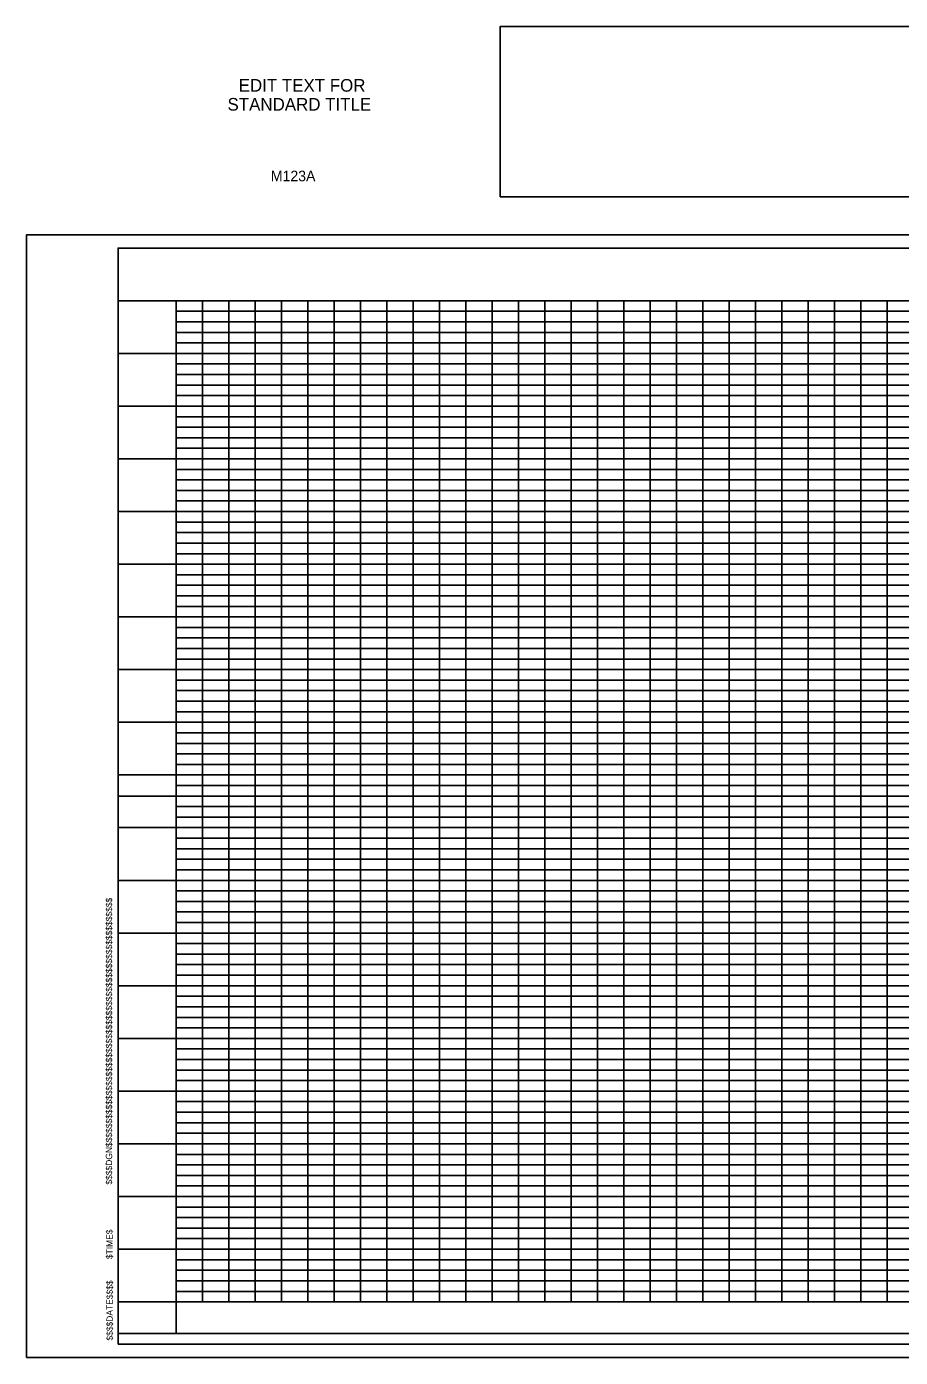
# Model space of a CAD drawing. Extents: x -87 to 1577, y -13 to 1250.
# Drawn here: x -87 to 742, y -13 to 1250 of the extents above; entities that cross this region are included whole.
import ezdxf

# ---------------------------------------------------------------- set-up
doc = ezdxf.new("R2010")
doc.units = 0
for name, color, linetype in [('D_CFL_Clip_Boundary_1', 7, 'Continuous'), ('D_CFL_Clip_Boundary_2', 7, 'Continuous'), ('D_CFL_Sheet_Border_ PlotShape', 7, 'Continuous'), ('D_CFL_Sheet_Border_Base', 7, 'Continuous'), ('D_CFL_Sheet_Border_Plan_Plan', 7, 'Continuous'), ('D_CFL_Sheet_Border_PnP', 7, 'Continuous'), ('D_CFL_Sheet_Border_Profile', 7, 'Continuous')]:
    doc.layers.add(name, color=color, linetype=linetype)

msp = doc.modelspace()

# ---------------------------------------------------------------- linework, layer by layer
at = {"layer": 'D_CFL_Clip_Boundary_1'}
msp.add_lwpolyline([(0, 520), (0, 1040), (1305, 1040), (1305, 1000), (1560, 1000), (1560, 520)], close=True, dxfattribs=at)
at = {"layer": 'D_CFL_Clip_Boundary_2'}
msp.add_lwpolyline([(1505, 520), (55, 520), (55, 40), (1505, 40)], close=True, dxfattribs=at)
at = {"layer": 'D_CFL_Sheet_Border_ PlotShape'}
msp.add_line((-86.9, -12.7), (-86.9, -12.7), dxfattribs=at)
msp.add_lwpolyline([(-86.9, -12.7), (1576.9, -12.7), (1576.9, 1052.6), (-86.9, 1052.6)], close=True, dxfattribs=at)
at = {"layer": 'D_CFL_Sheet_Border_Base'}
for points in [[(362.6, 1088.6), (1560, 1088.6), (1560, 1250.1), (362.6, 1250.1)], [(0, 0), (1560, 0), (1560, 1040), (0, 1040)]]:
    msp.add_lwpolyline(points, close=True, dxfattribs=at)
at = {"layer": 'D_CFL_Sheet_Border_Plan_Plan'}
msp.add_line((0, 520), (1560, 520), dxfattribs=at)
at = {"layer": 'D_CFL_Sheet_Border_PnP'}
for p, q in [((0, 520), (1560, 520)), ((55, 520), (55, 10)), ((80, 40), (80, 520)), ((105, 40), (105, 520)), ((130, 40), (130, 520)), ((155, 40), (155, 520)), ((180, 40), (180, 520)), ((205, 40), (205, 520)), ((230, 40), (230, 520)), ((255, 40), (255, 520)), ((280, 40), (280, 520)), ((305, 40), (305, 520)), ((330, 40), (330, 520)), ((355, 40), (355, 520)), ((380, 40), (380, 520)), ((405, 40), (405, 520)), ((430, 40), (430, 520)), ((455, 40), (455, 520)), ((480, 40), (480, 520)), ((505, 40), (505, 520)), ((530, 40), (530, 520)), ((555, 40), (555, 520)), ((580, 40), (580, 520)), ((605, 40), (605, 520)), ((630, 40), (630, 520)), ((655, 40), (655, 520)), ((680, 40), (680, 520)), ((705, 40), (705, 520)), ((730, 40), (730, 520)), ((55, 510), (1505, 510)), ((55, 500), (1505, 500)), ((55, 490), (0, 490)), ((55, 490), (1505, 490)), ((55, 480), (1505, 480)), ((55, 470), (1505, 470)), ((55, 460), (1505, 460)), ((55, 450), (1505, 450)), ((55, 440), (0, 440)), ((55, 440), (1505, 440)), ((55, 430), (1505, 430)), ((55, 420), (1505, 420)), ((55, 410), (1505, 410)), ((55, 400), (1505, 400)), ((55, 390), (0, 390)), ((55, 390), (1505, 390)), ((55, 380), (1505, 380)), ((55, 370), (1505, 370)), ((55, 360), (1505, 360)), ((55, 350), (1505, 350)), ((55, 340), (0, 340)), ((55, 340), (1505, 340)), ((55, 330), (1505, 330)), ((55, 320), (1505, 320)), ((55, 310), (1505, 310)), ((55, 300), (1505, 300)), ((55, 290), (0, 290)), ((55, 290), (1505, 290)), ((55, 280), (1505, 280)), ((55, 270), (1505, 270)), ((55, 260), (1505, 260)), ((55, 240), (0, 240)), ((55, 250), (1505, 250)), ((55, 240), (1505, 240)), ((55, 230), (1505, 230)), ((55, 220), (1505, 220)), ((55, 210), (1505, 210)), ((55, 190), (0, 190)), ((55, 200), (1505, 200)), ((55, 190), (1505, 190)), ((55, 180), (1505, 180)), ((55, 170), (1505, 170)), ((55, 160), (1505, 160)), ((55, 140), (0, 140)), ((55, 150), (1505, 150)), ((55, 140), (1505, 140)), ((55, 130), (1505, 130)), ((55, 120), (1505, 120)), ((55, 110), (1505, 110)), ((55, 90), (0, 90)), ((55, 100), (1505, 100)), ((55, 90), (1505, 90)), ((55, 80), (1505, 80)), ((55, 70), (1505, 70)), ((55, 60), (1505, 60)), ((55, 40), (0, 40)), ((55, 50), (1505, 50)), ((55, 40), (1505, 40)), ((0, 10), (1560, 10))]:
    msp.add_line(p, q, dxfattribs=at)
at = {"layer": 'D_CFL_Sheet_Border_Profile'}
for p, q in [((0, 990), (1560, 990)), ((55, 990), (55, 10)), ((80, 40), (80, 990)), ((105, 40), (105, 990)), ((130, 40), (130, 990)), ((155, 40), (155, 990)), ((180, 40), (180, 990)), ((205, 40), (205, 990)), ((230, 40), (230, 990)), ((255, 40), (255, 990)), ((280, 40), (280, 990)), ((305, 40), (305, 990)), ((330, 40), (330, 990)), ((355, 40), (355, 990)), ((380, 40), (380, 990)), ((405, 40), (405, 990)), ((430, 40), (430, 990)), ((455, 40), (455, 990)), ((480, 40), (480, 990)), ((505, 40), (505, 990)), ((530, 40), (530, 990)), ((555, 40), (555, 990)), ((580, 40), (580, 990)), ((605, 40), (605, 990)), ((630, 40), (630, 990)), ((655, 40), (655, 990)), ((680, 40), (680, 990)), ((705, 40), (705, 990)), ((730, 40), (730, 990)), ((55, 980), (1505, 980)), ((55, 970), (1505, 970)), ((55, 960), (1505, 960)), ((55, 950), (1505, 950)), ((55, 940), (0, 940)), ((55, 940), (1505, 940)), ((55, 930), (1505, 930)), ((55, 920), (1505, 920)), ((55, 910), (1505, 910)), ((55, 900), (1505, 900)), ((55, 890), (0, 890)), ((55, 890), (1505, 890)), ((55, 880), (1505, 880)), ((55, 870), (1505, 870)), ((55, 860), (1505, 860)), ((55, 850), (1505, 850)), ((55, 840), (0, 840)), ((55, 840), (1505, 840)), ((55, 830), (1505, 830)), ((55, 820), (1505, 820)), ((55, 810), (1505, 810)), ((55, 800), (1505, 800)), ((55, 790), (0, 790)), ((55, 790), (1505, 790)), ((55, 780), (1505, 780)), ((55, 770), (1505, 770)), ((55, 760), (1505, 760)), ((55, 750), (1505, 750)), ((55, 740), (0, 740)), ((55, 740), (1505, 740)), ((55, 730), (1505, 730)), ((55, 720), (1505, 720)), ((55, 710), (1505, 710)), ((55, 700), (1505, 700)), ((55, 690), (0, 690)), ((55, 690), (1505, 690)), ((55, 680), (1505, 680)), ((55, 670), (1505, 670)), ((55, 660), (1505, 660)), ((55, 650), (1505, 650)), ((55, 640), (0, 640)), ((55, 640), (1505, 640)), ((55, 630), (1505, 630)), ((55, 620), (1505, 620)), ((55, 610), (1505, 610)), ((55, 600), (1505, 600)), ((55, 590), (0, 590)), ((55, 590), (1505, 590)), ((55, 580), (1505, 580)), ((55, 570), (1505, 570)), ((55, 560), (1505, 560)), ((55, 550), (1505, 550)), ((55, 540), (0, 540)), ((55, 540), (1505, 540)), ((55, 530), (1505, 530)), ((55, 520), (1505, 520)), ((55, 510), (1505, 510)), ((55, 500), (1505, 500)), ((55, 490), (0, 490)), ((55, 490), (1505, 490)), ((55, 480), (1505, 480)), ((55, 470), (1505, 470)), ((55, 460), (1505, 460)), ((55, 450), (1505, 450)), ((55, 440), (0, 440)), ((55, 440), (1505, 440)), ((55, 430), (1505, 430)), ((55, 420), (1505, 420)), ((55, 410), (1505, 410)), ((55, 400), (1505, 400)), ((55, 390), (0, 390)), ((55, 390), (1505, 390)), ((55, 380), (1505, 380)), ((55, 370), (1505, 370)), ((55, 360), (1505, 360)), ((55, 350), (1505, 350)), ((55, 340), (0, 340)), ((55, 340), (1505, 340)), ((55, 330), (1505, 330)), ((55, 320), (1505, 320)), ((55, 310), (1505, 310)), ((55, 300), (1505, 300)), ((55, 290), (0, 290)), ((55, 290), (1505, 290)), ((55, 280), (1505, 280)), ((55, 270), (1505, 270)), ((55, 260), (1505, 260)), ((55, 240), (0, 240)), ((55, 250), (1505, 250)), ((55, 240), (1505, 240)), ((55, 230), (1505, 230)), ((55, 220), (1505, 220)), ((55, 210), (1505, 210)), ((55, 190), (0, 190)), ((55, 200), (1505, 200)), ((55, 190), (1505, 190)), ((55, 180), (1505, 180)), ((55, 170), (1505, 170)), ((55, 160), (1505, 160)), ((55, 140), (0, 140)), ((55, 150), (1505, 150)), ((55, 140), (1505, 140)), ((55, 130), (1505, 130)), ((55, 120), (1505, 120)), ((55, 110), (1505, 110)), ((55, 90), (0, 90)), ((55, 100), (1505, 100)), ((55, 90), (1505, 90)), ((55, 80), (1505, 80)), ((55, 70), (1505, 70)), ((55, 60), (1505, 60)), ((55, 40), (0, 40)), ((55, 50), (1505, 50)), ((55, 40), (1505, 40)), ((0, 10), (1560, 10))]:
    msp.add_line(p, q, dxfattribs=at)

# ---------------------------------------------------------------- texts
at = {"layer": 'D_CFL_Sheet_Border_Base'}
for s, height, p in [('EDIT TEXT FOR', 12, (114.4, 1188.4)), ('STANDARD TITLE', 12, (103.8, 1170.4)), ('M123A', 10, (144.9, 1103.4))]:
    msp.add_text(s, height=height, dxfattribs=at).set_placement(p)
for s, p in [('$$$$DGN$$$$$$$$$$$$$$$$$$$$$$$$$$$$$$$$$$$$$$$$$$$$$$$$$$$$$', (-5.7, 151.3)), ('$TIME$', (-5.3, 80.6)), ('$$$$DATE$$$$', (-5.1, 3.3))]:
    msp.add_text(s, height=6, rotation=90, dxfattribs=at).set_placement(p)

doc.saveas('drawing.dxf')
